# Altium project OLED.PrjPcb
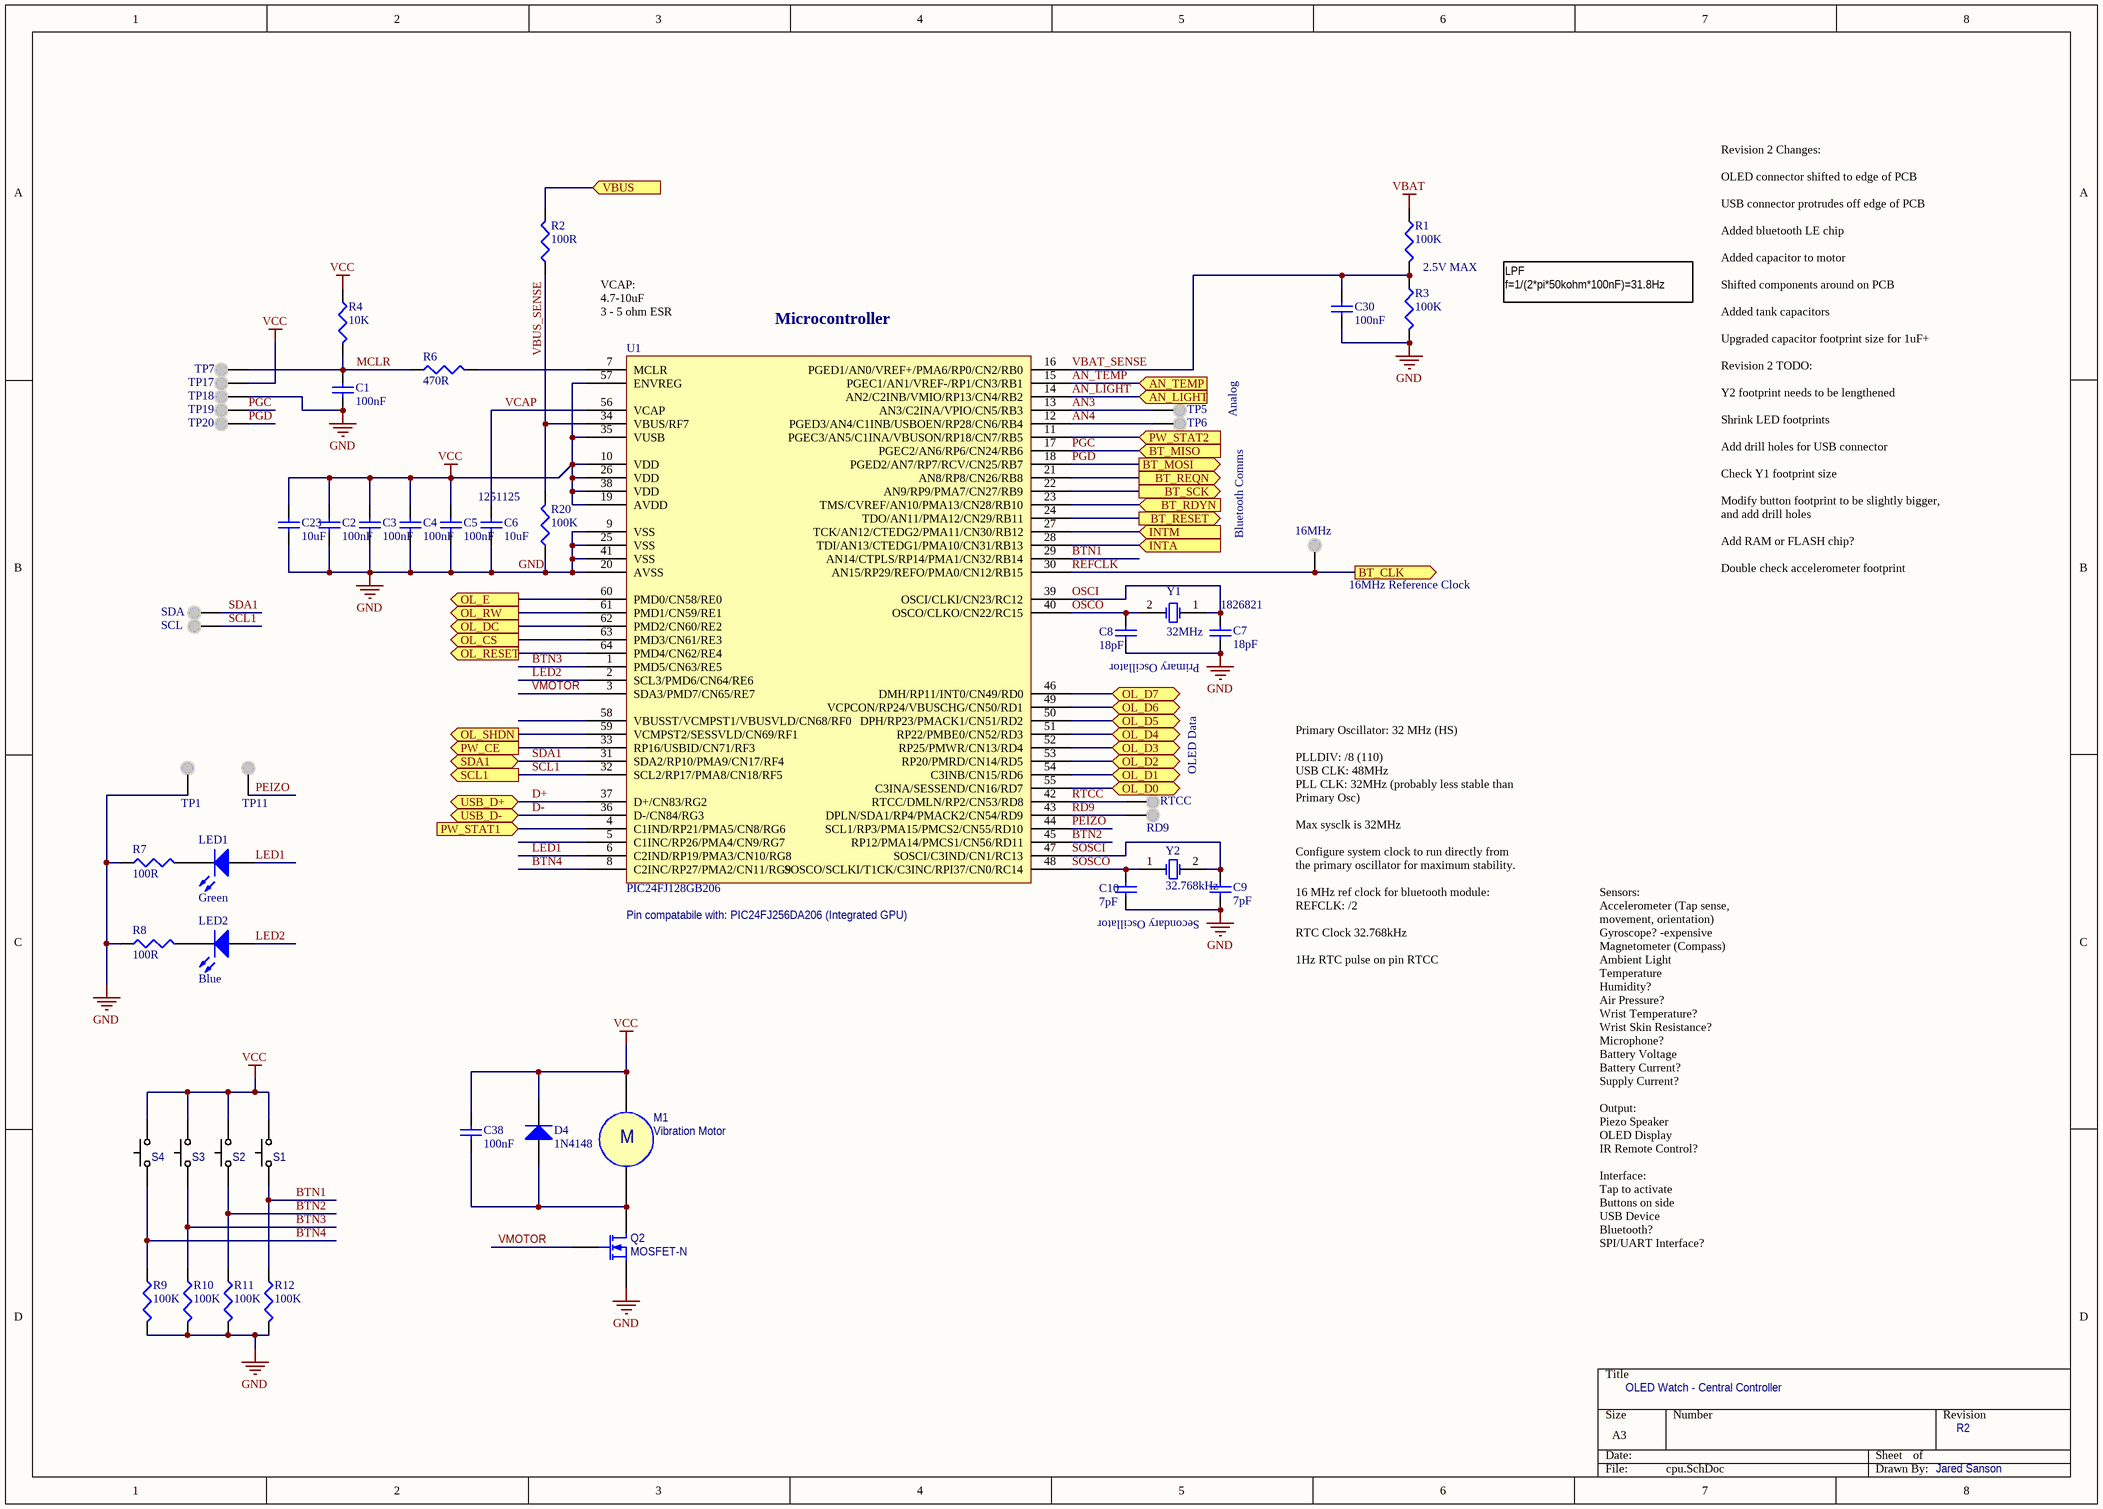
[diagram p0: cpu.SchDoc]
5 sheets, 121 parts. Net scope: flat (ports and power ports of the same name join across sheets).
Board file: pcb.PcbDoc
Sheets:
  cpu.SchDoc
  power.SchDoc
  oled.SchDoc
  sensors.SchDoc
  bluetoothle.SchDoc

## Sheet cpu.SchDoc
size A3

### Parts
C1  value 100nF  [0603C]  (hidden comment: Cap)
C2  value 100nF  [0603C]  (hidden comment: Cap)
C3  value 100nF  [0603C]  (hidden comment: Cap)
C4  value 100nF  [0603C]  (hidden comment: Cap)
C5  value 100nF  [0603C]  (hidden comment: Cap)
C6  value 10uF  Supplier Part Number 1: 1251125  [0805C]  (hidden comment: Cap)
C7  value 18pF  [0603C]  (hidden comment: Cap)
C8  value 18pF  [0603C]  (hidden comment: Cap)
C9  value 7pF  [0603C]  (hidden comment: Cap)
C10  value 7pF  [0603C]  (hidden comment: Cap)
C23  value 10uF  [0805C]  (hidden comment: Cap)
C30  value 100nF  [0603C]  (hidden comment: Cap)
C38  value 100nF  [0603C]  (hidden comment: Cap)
D4  1N4148  [0603D]
LED1  Green  [0603LED]
LED2  Blue  [0603LED]
M1  Vibration Motor  [VIBRATION_MOTOR]
OSC  16MHz  [TESTPOINT_TOP]
Q2  MOSFET-N  [SOT-23B_N]
R1  value 100K  [0603R]  (hidden comment: Res3)
R2  value 100R  [0603R]  (hidden comment: Res3)
R3  value 100K  [0603R]  (hidden comment: Res3)
R4  value 10K  [0603R]  (hidden comment: Res3)
R6  value 470R  [0603R]  (hidden comment: Res3)
R7  value 100R  [0603R]  (hidden comment: Res3)
R8  value 100R  [0603R]  (hidden comment: Res3)
R9  value 100K  [0603R]  (hidden comment: Res3)
R10  value 100K  [0603R]  (hidden comment: Res3)
R11  value 100K  [0603R]  (hidden comment: Res3)
R12  value 100K  [0603R]  (hidden comment: Res3)
R20  value 100K  [0603R]  (hidden comment: Res3)
RD9  (no value)  [TESTPOINT_TOP]
RTCC  RTCC  [TESTPOINT_TOP]  (value not drawn)
S1  SideButton  [SIDE_BUTTON]  (value not drawn)
S2  SideButton  [SIDE_BUTTON]  (value not drawn)
S3  SideButton  [SIDE_BUTTON]  (value not drawn)
S4  SideButton  [SIDE_BUTTON]  (value not drawn)
SCL  SCL  [TESTPOINT_TOP]  (value not drawn)
SDA  SDA  [TESTPOINT_TOP]  (value not drawn)
TP1  PZ-  [TESTPOINT_TOP]  (value not drawn)
TP5  AN4  [TESTPOINT_TOP]  (value not drawn)
TP6  AN5  [TESTPOINT_TOP]  (value not drawn)
TP7  MCLR  [TESTPOINT_TOP]  (value not drawn)
TP11  PZ+  [TESTPOINT_TOP]  (value not drawn)
TP17  VCC  [TESTPOINT_TOP]  (value not drawn)
TP18  GND  [TESTPOINT_TOP]  (value not drawn)
TP19  PGC  [TESTPOINT_TOP]  (value not drawn)
TP20  PGD  [TESTPOINT_TOP]  (value not drawn)
U1  PIC24FJ128GB206  [TQFP_64_10MM]
Y1  32MHz  Supplier Part Number 1: 1826821  [ABRACON32MHZ]
Y2  32.768kHz  [BCY-W2/D1.5]

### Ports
AN_LIGHT (in), AN_TEMP (in), BT_CLK (out), BT_MISO (in), BT_MOSI (out), BT_RDYN (in), BT_REQN (out), BT_RESET (out), BT_SCK (out), INTA (in), INTM (in), OL_CS (out), OL_D0 (bidir), OL_D1 (bidir), OL_D2 (bidir), OL_D3 (bidir), OL_D4 (bidir), OL_D5 (bidir), OL_D6 (bidir), OL_D7 (bidir), OL_DC (out), OL_E (out), OL_RESET (out), OL_RW (out), OL_SHDN (out), PW_CE (out), PW_STAT1 (in), PW_STAT2 (in), SCL1 (out), SDA1 (bidir), USB_D+ (bidir), USB_D- (bidir), VBUS (in)

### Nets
GND: C1.2 C2.2 C3.2 C4.2 C5.2 C6.2 C7.2 C8.2 C9.2 C10.2 C23.2 C30.2 Q2.3(S) R3.2 R7.1 R8.1 R9.2 R10.2 R11.2 R12.2 R20.1 TP1.1(TP) TP18.1(TP) U1.9(VSS) U1.20(AVSS) U1.25(VSS) U1.41(VSS)
VBAT: R1.1
VCC: C2.1 C3.1 C4.1 C5.1 C23.1 C38.1 D4.2(K) M1.1 R4.1 S1.2 S2.2 S3.2 S4.2 TP17.1(TP) U1.10(VDD) U1.19(AVDD) U1.26(VDD) U1.35(VUSB) U1.38(VDD) U1.57(ENVREG)
AN3: TP5.1(TP) U1.13(AN3/C2INA/VPIO/CN5/RB3)
AN4: TP6.1(TP) U1.12(PGED3/AN4/C1INB/USBOEN/RP28/CN6/RB4)
AN_LIGHT: U1.14(AN2/C2INB/VMIO/RP13/CN4/RB2) ; port AN_LIGHT
AN_TEMP: U1.15(PGEC1/AN1/VREF-/RP1/CN3/RB1) ; port AN_TEMP
BT_RDYN: U1.23(TMS/CVREF/AN10/PMA13/CN28/RB10) ; port BT_RDYN
BT_REQN: U1.21(AN8/RP8/CN26/RB8) ; port BT_REQN
BTN1: R12.1 S1.1 U1.29(AN14/CTPLS/RP14/PMA1/CN32/RB14)
BTN2: R11.1 S2.1 U1.45(RP12/PMA14/PMCS1/CN56/RD11)
BTN3: R10.1 S3.1 U1.1(PMD5/CN63/RE5)
BTN4: R9.1 S4.1 U1.8(C2INC/RP27/PMA2/CN11/RG9)
D+: U1.37(D+/CN83/RG2) ; port USB_D+
D-: U1.36(D-/CN84/RG3) ; port USB_D-
INTA: U1.28(TDI/AN13/CTEDG1/PMA10/CN31/RB13) ; port INTA
INTM: U1.27(TCK/AN12/CTEDG2/PMA11/CN30/RB12) ; port INTM
LED1: LED1.1(A) U1.6(C2IND/RP19/PMA3/CN10/RG8)
LED2: LED2.1(A) U1.2(SCL3/PMD6/CN64/RE6)
MCLR: C1.1 R4.2 R6.1 TP7.1(TP)
OL_CS: U1.63(PMD3/CN61/RE3) ; port OL_CS
OL_D0: U1.55(C3INA/SESSEND/CN16/RD7) ; port OL_D0
OL_D1: U1.54(C3INB/CN15/RD6) ; port OL_D1
OL_D2: U1.53(RP20/PMRD/CN14/RD5) ; port OL_D2
OL_D3: U1.52(RP25/PMWR/CN13/RD4) ; port OL_D3
OL_D4: U1.51(RP22/PMBE0/CN52/RD3) ; port OL_D4
OL_D5: U1.50(DPH/RP23/PMACK1/CN51/RD2) ; port OL_D5
OL_D6: U1.49(VCPCON/RP24/VBUSCHG/CN50/RD1) ; port OL_D6
OL_D7: U1.46(DMH/RP11/INT0/CN49/RD0) ; port OL_D7
OL_DC: U1.62(PMD2/CN60/RE2) ; port OL_DC
OL_E: U1.60(PMD0/CN58/RE0) ; port OL_E
OL_RESET: U1.64(PMD4/CN62/RE4) ; port OL_RESET
OL_RW: U1.61(PMD1/CN59/RE1) ; port OL_RW
OL_SHDN: U1.59(VCMPST2/SESSVLD/CN69/RF1) ; port OL_SHDN
OSCI: C7.1 U1.39(OSCI/CLKI/CN23/RC12) Y1.1(OSC1)
OSCO: C8.1 U1.40(OSCO/CLKO/CN22/RC15) Y1.2(OSC2)
PEIZO: TP11.1(TP) U1.44(SCL1/RP3/PMA15/PMCS2/CN55/RD10)
PGC: TP19.1(TP) U1.17(PGEC2/AN6/RP6/CN24/RB6) ; port BT_MISO
PGD: TP20.1(TP) U1.18(PGED2/AN7/RP7/RCV/CN25/RB7) ; port BT_MOSI
PW_CE: U1.33(RP16/USBID/CN71/RF3) ; port PW_CE
RD9: RD9.1(TP) U1.43(DPLN/SDA1/RP4/PMACK2/CN54/RD9)
REFCLK: OSC.1(TP) U1.30(AN15/RP29/REFO/PMA0/CN12/RB15) ; port BT_CLK
RESET: U1.24(TDO/AN11/PMA12/CN29/RB11) ; port BT_RESET
RTCC: RTCC.1(TP) U1.42(RTCC/DMLN/RP2/CN53/RD8)
SCK: U1.22(AN9/RP9/PMA7/CN27/RB9) ; port BT_SCK
SCL1: SCL.1(TP) U1.32(SCL2/RP17/PMA8/CN18/RF5) ; port SCL1
SDA1: SDA.1(TP) U1.31(SDA2/RP10/PMA9/CN17/RF4) ; port SDA1
SOSCI: C9.1 U1.47(SOSCI/C3IND/CN1/RC13) Y2.2(OSC2)
SOSCO: C10.1 U1.48(SOSCO/SCLKI/T1CK/C3INC/RPI37/CN0/RC14) Y2.1(OSC1)
STAT1: U1.4(C1IND/RP21/PMA5/CN8/RG6) ; port PW_STAT1
STAT2: U1.11(PGEC3/AN5/C1INA/VBUSON/RP18/CN7/RB5) ; port PW_STAT2
VBAT_SENSE: C30.1 R1.2 R3.1 U1.16(PGED1/AN0/VREF+/PMA6/RP0/CN2/RB0)
VBUS: R2.2 ; port VBUS
VBUS_SENSE: R2.1 R20.2 U1.34(VBUS/RF7)
VCAP: C6.1 U1.56(VCAP)
VMOTOR: Q2.2(G) U1.3(SDA3/PMD7/CN65/RE7)
NetC38_2: C38.2 D4.1(A) M1.2 Q2.1(D)
NetLED1_2: LED1.2(K) R7.2
NetLED2_2: LED2.2(K) R8.2
NetR6_2: R6.2 U1.7(MCLR)

Not connected (* = marked no-connect by the designer): U1 5(C1INC/RP26/PMA4/CN9/RG7) 58(VBUSST/VCMPST1/VBUSVLD/CN68/RF0)

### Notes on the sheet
- 2.5V MAX
- LPF
  f=1/(2*pi*50kohm*100nF)=31.8Hz
- VCAP:
  4.7-10uF
  3 - 5 ohm ESR
- (near U1) Microcontroller
- Analog
- Bluetooth Comms
- (near OSC) 16MHz Reference Clock
- Primary Oscillator
- OLED Data
- Revision 2 Changes:
  OLED connector shifted to edge of PCB
  USB connector protrudes off edge of PCB
  Added bluetooth LE chip
  Added capacitor to motor
  Shifted components around on PCB
  Added tank capacitors
  Upgraded capacitor footprint size for 1uF+
  Revision 2 TODO:
  Y2 footprint needs to be lengthened
  Shrink LED footprints
  Add drill holes for USB connector
  Check Y1 footprint size
  Modify button footprint to be slightly bigger, and add drill holes
  Add RAM or FLASH chip?
  Double check accelerometer footprint
- (near U1) Pin compatabile with: PIC24FJ256DA206 (Integrated GPU)
- Secondary Oscillator
- Primary Oscillator: 32 MHz (HS)
  PLLDIV: /8 (110)
  USB CLK: 48MHz
  PLL CLK: 32MHz (probably less stable than Primary Osc)
  Max sysclk is 32MHz
  Configure system clock to run directly from the primary oscillator for maximum stability.
  16 MHz ref clock for bluetooth module:
  REFCLK: /2
  RTC Clock 32.768kHz
  1Hz RTC pulse on pin RTCC
- Sensors:
  Accelerometer (Tap sense, movement, orientation)
  Gyroscope? -expensive
  Magnetometer (Compass)
  Ambient Light
  Temperature
  Humidity?
  Air Pressure?
  Wrist Temperature?
  Wrist Skin Resistance?
  Microphone?
  Battery Voltage
  Battery Current?
  Supply Current?
  Output:
  Piezo Speaker
  OLED Display
  IR Remote Control?
  Interface:
  Tap to activate
  Buttons on side
  USB Device
  Bluetooth?
  SPI/UART Interface?
- OLED Watch - Central Controller
- R2
- Jared Sanson

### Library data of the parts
C1-C10 C23 C30 C38 = Cap: Capacitor
D4 = Diode: Default Diode
LED1 LED2 = LED2: Typical RED, GREEN, YELLOW, AMBER GaAs LED
M1 = VibrationMotor
OSC RD9 RTCC SCL SDA TP1 TP5-TP7 TP11 TP17-TP20 = TestPoint: Test Point
Q2 = MOSFET-N: N-Channel MOSFET
R1-R4 R6-R12 R20 = Res3: Resistor
Y1 = XTAL: Crystal Oscillator; Manufacturer: ABRACON; Manufacturer Part Number: ABM3-32.000MHZ-D2Y-T; Description: ABRACON - ABM3-32.000MHZ-D2Y-T - CRYSTAL, 32MHZ, 18PF, SMD
Y2 = XTAL: Crystal Oscillator

## Sheet power.SchDoc
size A4
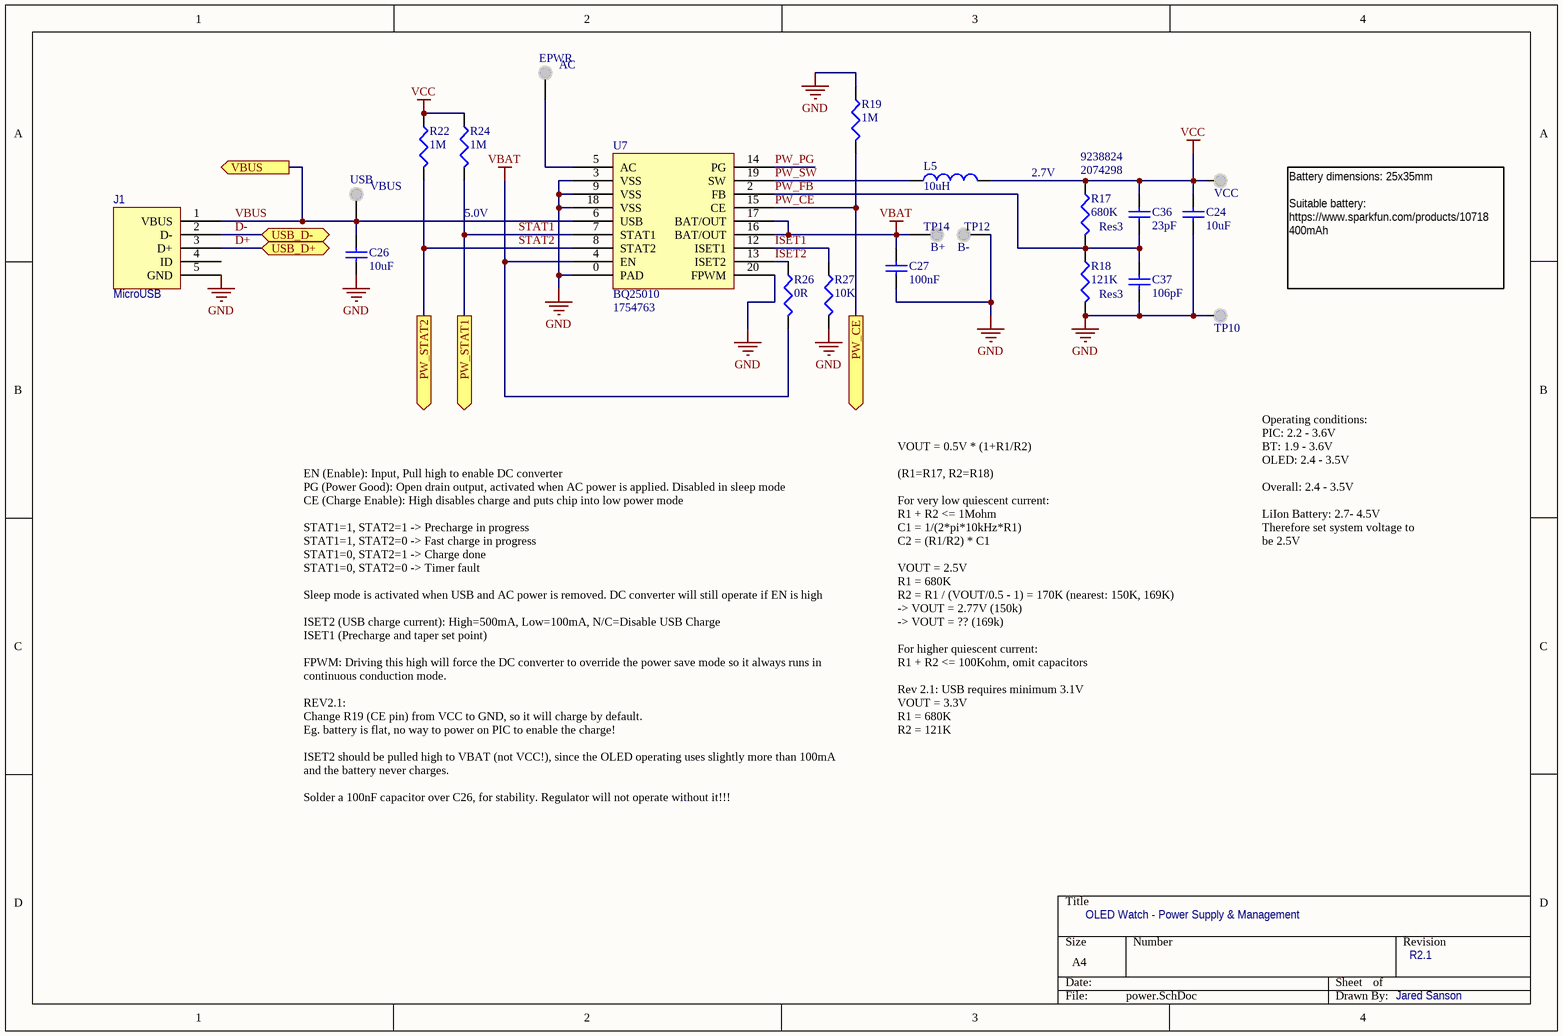
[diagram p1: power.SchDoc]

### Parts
C24  value 10uF  [0805C]  (hidden comment: Cap)
C26  value 10uF  [0805C]  (hidden comment: Cap)
C27  value 100nF  [0603C]  (hidden comment: Cap)
C36  value 23pF  [0603C]  (hidden comment: Cap)
C37  value 106pF  [0603C]  (hidden comment: Cap)
EPWR  AC  [TESTPOINT_TOP]
J1  MicroUSB  [MICRO_USB]
L5  value 10uH  [INDC3225N]  (hidden comment: Inductor)
R17  Res3  value 680K  Supplier Part Number 1: 2074298  Supplier Part Number 2: 9238824  [0603R]
R18  Res3  value 121K  [0603R]
R19  value 1M  [0603R]  (hidden comment: Res3)
R22  value 1M  [0603R]  (hidden comment: Res3)
R24  value 1M  [0603R]  (hidden comment: Res3)
R26  value 0R  [0603R]  (hidden comment: Res3)
R27  value 10K  [0603R]  (hidden comment: Res3)
TP10  GND  [TESTPOINT_TOP]  (value not drawn)
TP12  B-  [TESTPOINT_TOP]
TP14  B+  [TESTPOINT_TOP]
U7  BQ25010  Supplier Part Number 1: 1754763  [RHL]
USB  VBUS  [TESTPOINT_TOP]
VCC  VCC  [TESTPOINT_TOP]  (value not drawn)

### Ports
PW_CE (out), PW_STAT1 (out), PW_STAT2 (out), USB_D+ (bidir), USB_D- (bidir), VBUS (out)

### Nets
GND: C24.2 C26.2 C27.2 C37.2 J1.5(GND) R18.2 R19.1 R27.2 TP10.1(TP) TP12.1(TP) U7.0(PAD) U7.3(VSS) U7.9(VSS) U7.18(VSS) U7.20(FPWM)
VBAT: C27.1 R26.2 TP14.1(TP) U7.4(EN) U7.16(BAT/OUT) U7.17(BAT/OUT)
VCC: C24.1 C36.1 L5.2 R17.1 R22.1 R24.1 VCC.1(TP)
D+: J1.3(D+) ; port USB_D+
D-: J1.2(D-) ; port USB_D-
ISET1: R27.1 U7.12(ISET1)
ISET2: R26.1 U7.13(ISET2)
PW_CE: R19.2 U7.15(CE) ; port PW_CE
PW_FB: C36.2 C37.1 R17.2 R18.1 U7.2(FB)
PW_PG: U7.14(PG)
PW_SW: L5.1 U7.19(SW)
STAT1: R24.2 U7.7(STAT1) ; port PW_STAT1
STAT2: R22.2 U7.8(STAT2) ; port PW_STAT2
VBUS: C26.1 J1.1(VBUS) U7.6(USB) USB.1(TP) ; port VBUS
NetEPWR_1: EPWR.1(TP) U7.5(AC)

Not connected (* = marked no-connect by the designer): J1 4(ID)

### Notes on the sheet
- (near R17) 2.7V
- 5.0V
- Battery dimensions: 25x35mm
  Suitable battery:
  https://www.sparkfun.com/products/10718
  400mAh
- Operating conditions:
  PIC: 2.2 - 3.6V
  BT: 1.9 - 3.6V
  OLED: 2.4 - 3.5V
  Overall: 2.4 - 3.5V
  LiIon Battery: 2.7- 4.5V
  Therefore set system voltage to be 2.5V
- VOUT = 0.5V * (1+R1/R2)
  (R1=R17, R2=R18)
  For very low quiescent current:
  R1 + R2 <= 1Mohm
  C1 = 1/(2*pi*10kHz*R1)
  C2 = (R1/R2) * C1
  VOUT = 2.5V
  R1 = 680K
  R2 = R1 / (VOUT/0.5 - 1) = 170K (nearest: 150K, 169K)
  -> VOUT = 2.77V (150k)
  -> VOUT = ?? (169k)
  For higher quiescent current:
  R1 + R2 <= 100Kohm, omit capacitors
  Rev 2.1: USB requires minimum 3.1V
  VOUT = 3.3V
  R1 = 680K
  R2 = 121K
- EN (Enable): Input, Pull high to enable DC converter
  PG (Power Good): Open drain output, activated when AC power is applied. Disabled in sleep mode
  CE (Charge Enable): High disables charge and puts chip into low power mode
  STAT1=1, STAT2=1 -> Precharge in progress
  STAT1=1, STAT2=0 -> Fast charge in progress
  STAT1=0, STAT2=1 -> Charge done
  STAT1=0, STAT2=0 -> Timer fault
  Sleep mode is activated when USB and AC power is removed. DC converter will still operate if EN is high
  ISET2 (USB charge current): High=500mA, Low=100mA, N/C=Disable USB Charge
  ISET1 (Precharge and taper set point)
  FPWM: Driving this high will force the DC converter to override the power save mode so it always runs in continuous conduction mode.
  REV2.1:
  Change R19 (CE pin) from VCC to GND, so it will charge by default.
  Eg. battery is flat, no way to power on PIC to enable the charge!
  ISET2 should be pulled high to VBAT (not VCC!), since the OLED operating uses slightly more than 100mA and the battery never charges.
  Solder a 100nF capacitor over C26, for stability. Regulator will not operate without it!!!
- OLED Watch - Power Supply & Management
- R2.1
- Jared Sanson

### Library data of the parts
C24 C26 C27 C36 C37 = Cap: Capacitor
EPWR TP10 TP12 TP14 USB VCC = TestPoint: Test Point
L5 = Inductor: Code_IEC: 1005
R17-R19 R22 R24 R26 R27 = Res3: Resistor

## Sheet oled.SchDoc
size A4
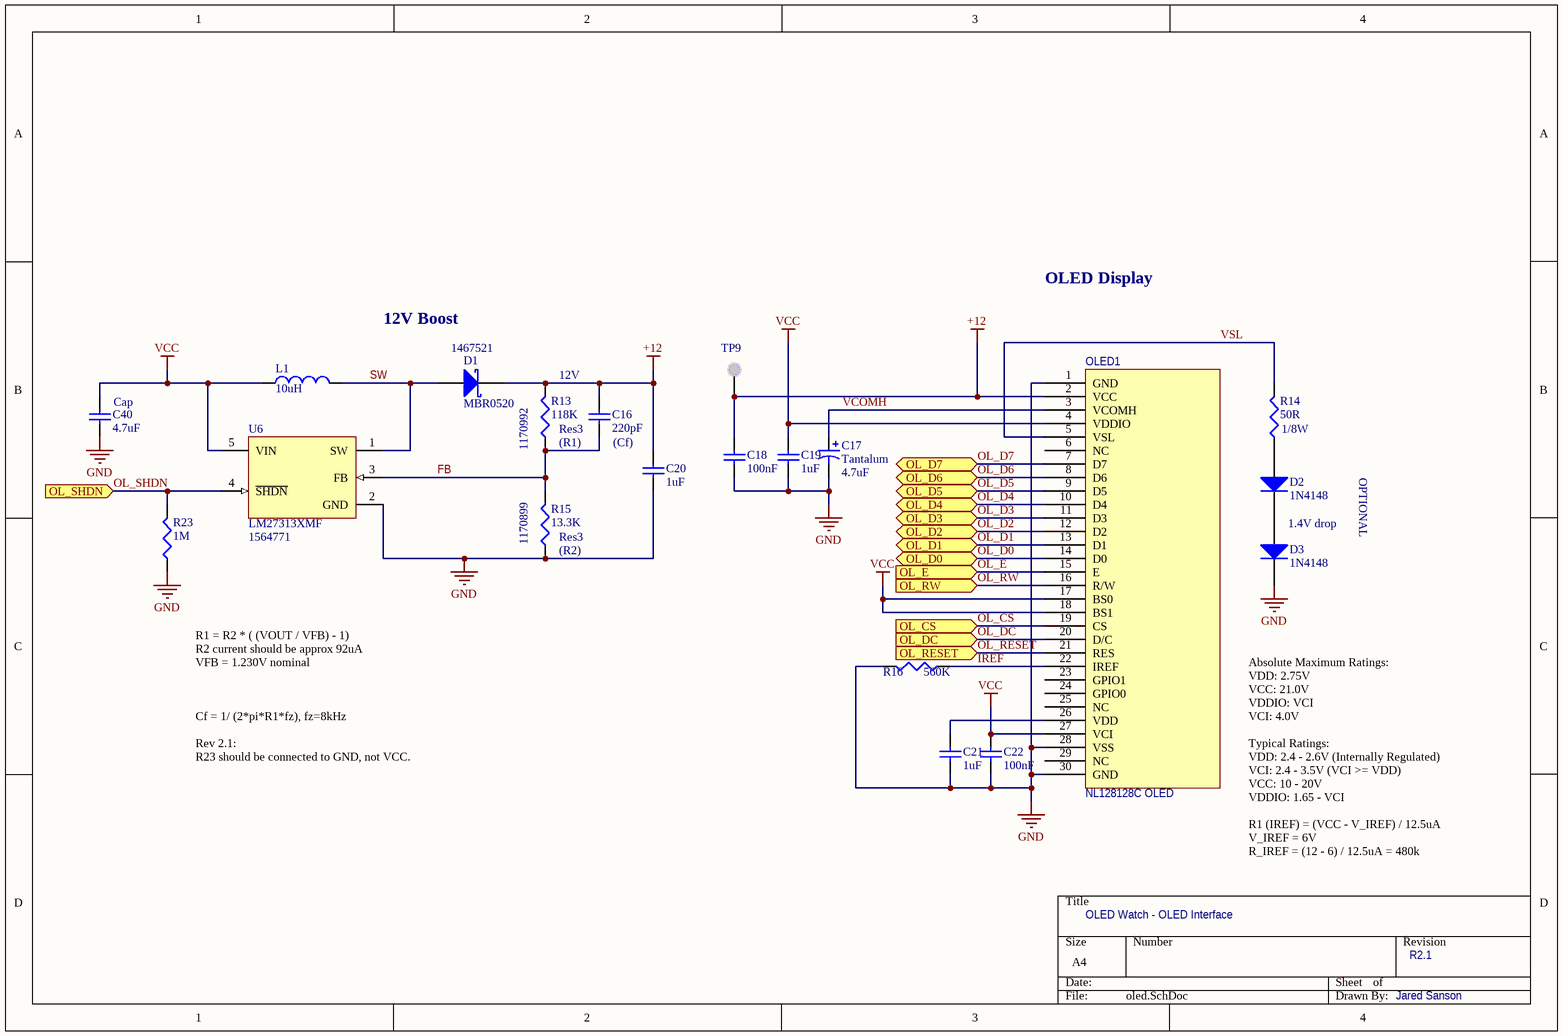
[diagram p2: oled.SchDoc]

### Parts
C16  value 220pF  Variable: (Cf)  [0603C]  (hidden comment: Cap)
C17  Tantalum  value 4.7uF  [0805C]
C18  value 100nF  [0603C]  (hidden comment: Cap)
C19  value 1uF  [0603C]  (hidden comment: Cap)
C20  value 1uF  [0805C]  (hidden comment: Cap)
C21  value 1uF  [0805C]  (hidden comment: Cap)
C22  value 100nF  [0603C]  (hidden comment: Cap)
C40  Cap  value 4.7uF  [0805C]
D1  MBR0520  Supplier Part Number 1: 1467521  [0603D]
D2  1N4148  [0603D]
D3  1N4148  [0603D]
L1  value 10uH  [INDC3225N]  (hidden comment: Inductor)
OLED1  NL128128C OLED  [FFC/SM0.5-2H30]
R13  Res3  value 118K  Variable: (R1)  Supplier Part Number 1: 1170992  [0603R]
R14  value 50R  [0603R]  (hidden comment: Res3)
R15  Res3  value 13.3K  Variable: (R2)  Supplier Part Number 1: 1170899  [0603R]
R16  value 560K  [0603R]  (hidden comment: Res3)
R23  value 1M  [0603R]  (hidden comment: Res3)
TP9  +12  [TESTPOINT_TOP]  (value not drawn)
U6  LM27313XMF  Supplier Part Number 1: 1564771  [MF05A_N]

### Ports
OL_CS (in), OL_D0 (bidir), OL_D1 (bidir), OL_D2 (bidir), OL_D3 (bidir), OL_D4 (bidir), OL_D5 (bidir), OL_D6 (bidir), OL_D7 (bidir), OL_DC (in), OL_E (in), OL_RESET (in), OL_RW (in), OL_SHDN (in)

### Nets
+12: C16.1 C18.1 C20.1 D1.2(K) OLED1.2(VCC) R13.2 TP9.1(TP)
GND: C17.2 C18.2 C19.2 C20.2 C21.2 C22.2 C40.2 D3.2(K) OLED1.1(GND) OLED1.28(VSS) OLED1.30(GND) R15.1 R16.2 R23.1 U6.2(GND)
VCC: C19.1 C22.1 C40.1 L1.1 OLED1.4(VDDIO) OLED1.17(BS0) OLED1.18(BS1) OLED1.27(VCI) U6.5(VIN)
FB: C16.2 R13.1 R15.2 U6.3(FB)
IREF: OLED1.22(IREF) R16.1
OL_CS: OLED1.19(CS) ; port OL_CS
OL_D0: OLED1.14(D0) ; port OL_D0
OL_D1: OLED1.13(D1) ; port OL_D1
OL_D2: OLED1.12(D2) ; port OL_D2
OL_D3: OLED1.11(D3) ; port OL_D3
OL_D4: OLED1.10(D4) ; port OL_D4
OL_D5: OLED1.9(D5) ; port OL_D5
OL_D6: OLED1.8(D6) ; port OL_D6
OL_D7: OLED1.7(D7) ; port OL_D7
OL_DC: OLED1.20(D/C) ; port OL_DC
OL_E: OLED1.15(E) ; port OL_E
OL_RESET: OLED1.21(RES) ; port OL_RESET
OL_RW: OLED1.16(R/W) ; port OL_RW
OL_SHDN: R23.2 U6.4(~{SHDN}) ; port OL_SHDN
SW: D1.1(A) L1.2 U6.1(SW)
VCOMH: C17.1 OLED1.3(VCOMH)
VSL: OLED1.5(VSL) R14.2
NetC21_1: C21.1 OLED1.26(VDD)
NetD2_1: D2.1(A) R14.1
NetD2_2: D2.2(K) D3.1(A)

Not connected (* = marked no-connect by the designer): OLED1 6(NC) 23(GPIO1) 24(GPIO0) 25(NC) 29(NC)

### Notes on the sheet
- OLED Display
- 12V Boost
- (near R13) 12V
- (near R14) 1/8W
- OPTIONAL
- 1.4V drop
- R1 = R2 * ( (VOUT / VFB) - 1)
  R2 current should be approx 92uA
  VFB = 1.230V nominal
  Cf = 1/ (2*pi*R1*fz), fz=8kHz
  Rev 2.1:
  R23 should be connected to GND, not VCC.
- OLED Watch - OLED Interface
- Absolute Maximum Ratings:
  VDD: 2.75V
  VCC: 21.0V
  VDDIO: VCI
  VCI: 4.0V
  Typical Ratings:
  VDD: 2.4 - 2.6V (Internally Regulated)
  VCI: 2.4 - 3.5V (VCI >= VDD)
  VCC: 10 - 20V
  VDDIO: 1.65 - VCI
  R1 (IREF) = (VCC - V_IREF) / 12.5uA
  V_IREF = 6V
  R_IREF = (12 - 6) / 12.5uA = 480k
- R2.1
- Jared Sanson

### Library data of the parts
C16 C18-C22 C40 = Cap: Capacitor
C17 = Cap Pol1: Polarized Capacitor (Radial)
D1 = D Schottky: Schottky Diode
D2 D3 = Diode: Default Diode
L1 = Inductor: Code_IEC: 1005
OLED1 = NL128128C: 128x128 OLED Display
R13-R16 R23 = Res3: Resistor
TP9 = TestPoint: Test Point
U6 = LM27313XMF: 1.6 MHz Boost Converter With 30V Internal FET Switch in SOT-23; Manufacturer: National Semiconductor; CompType: Switcher; PackageTopMarking: SRPB*XTT; PowerWise: N

## Sheet sensors.SchDoc
size A4
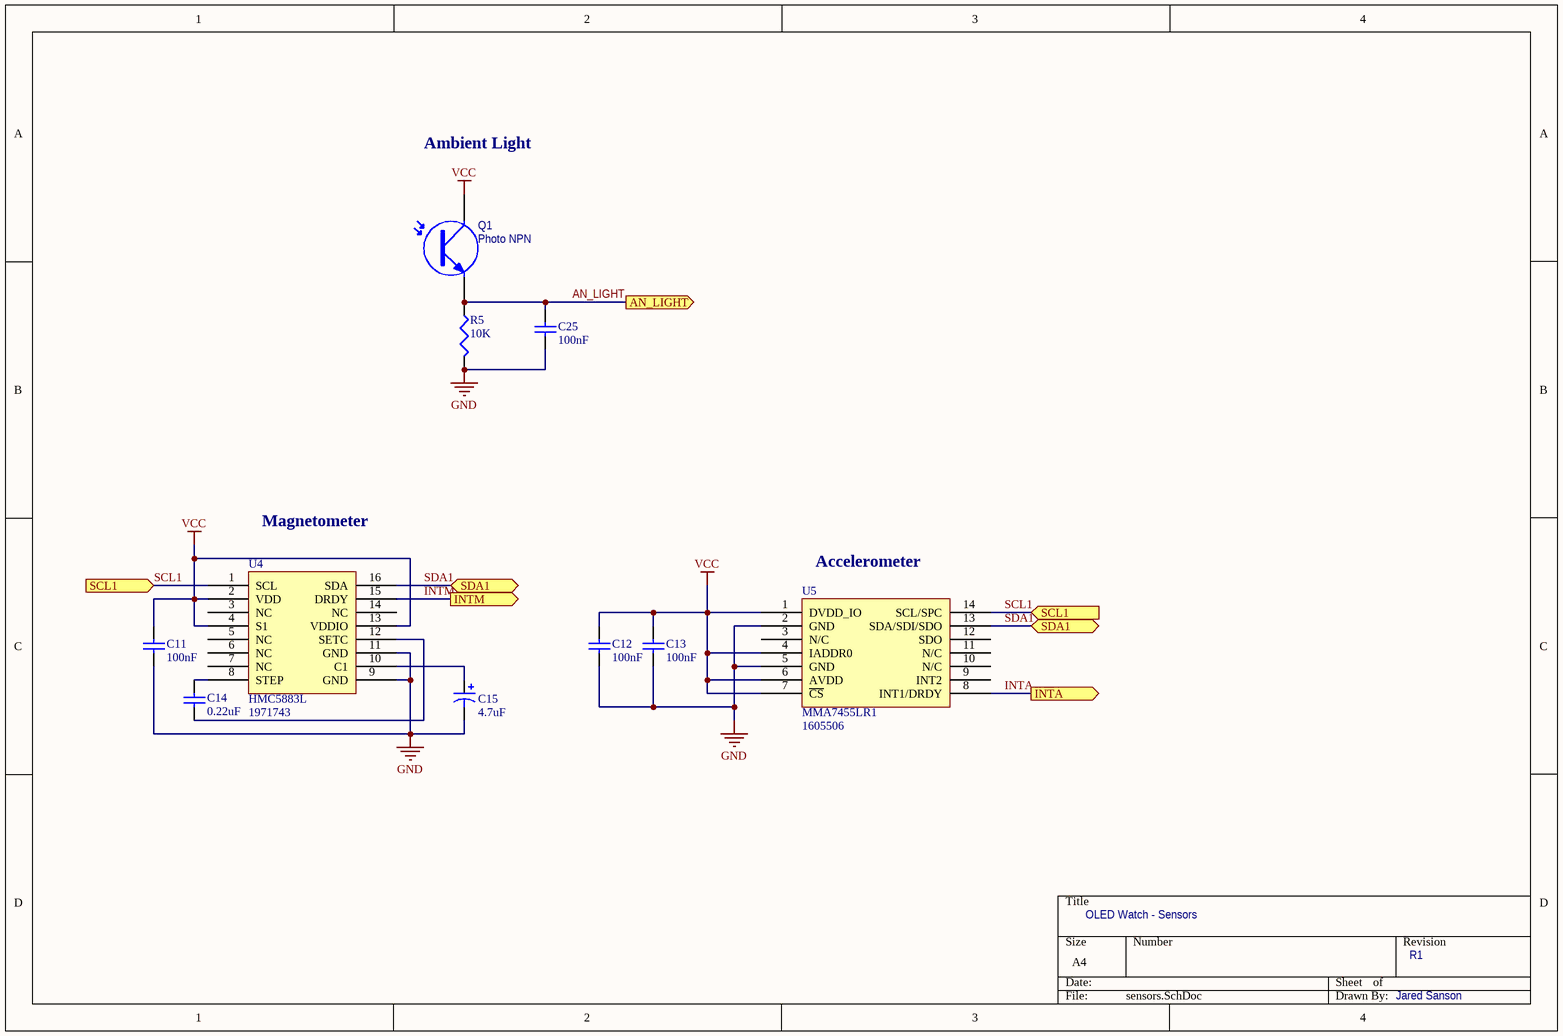
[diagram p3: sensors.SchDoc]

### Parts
C11  value 100nF  [0603C]  (hidden comment: Cap)
C12  value 100nF  [0603C]  (hidden comment: Cap)
C13  value 100nF  [0603C]  (hidden comment: Cap)
C14  value 0.22uF  [0603C]  (hidden comment: Cap)
C15  value 4.7uF  [0805C]  (hidden comment: Cap Pol1)
C25  value 100nF  [0603C]  (hidden comment: Cap)
Q1  Photo NPN  [TEMT6000]
R5  value 10K  [0603R]  (hidden comment: Res3)
U4  HMC5883L  Supplier Part Number 1: 1971743  [HMC5883L_16PINQFN]
U5  MMA7455LR1  Supplier Part Number 1: 1605506  [LGA80P500X300-14N]

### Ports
AN_LIGHT (out), INTA (out), INTM (out), SCL1 (in), SDA1 (bidir)

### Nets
GND: C11.2 C12.2 C13.2 C15.2 C25.2 R5.2 U4.9(GND) U4.11(GND) U5.2(GND) U5.5(GND)
VCC: C11.1 C12.1 C13.1 Q1.1(C) U4.2(VDD) U4.4(S1) U4.13(VDDIO) U5.1(DVDD_IO) U5.4(IADDR0) U5.6(AVDD) U5.7(~{CS})
AN_LIGHT: C25.1 Q1.3(E) R5.1 ; port AN_LIGHT
INTA: U5.8(INT1/DRDY) ; port INTA
INTM: U4.15(DRDY) ; port INTM
SCL1: U4.1(SCL) U5.14(SCL/SPC) ; port SCL1
SDA1: U4.16(SDA) U5.13(SDA/SDI/SDO) ; port SDA1
NetC14_1: C14.1 U4.12(SETC)
NetC14_2: C14.2 U4.8(STEP)
NetC15_1: C15.1 U4.10(C1)

Not connected (* = marked no-connect by the designer): U4 3(NC) 5(NC) 6(NC) 7(NC) 14(NC); U5 3(N/C) 9(INT2) 10(N/C) 11(N/C) 12(SDO)

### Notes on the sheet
- Ambient Light
- Magnetometer
- (near U5) Accelerometer
- OLED Watch - Sensors
- R1
- Jared Sanson

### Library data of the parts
C11-C14 C25 = Cap: Capacitor
C15 = Cap Pol1: Polarized Capacitor (Radial)
Q1 = Photo NPN: NPN Phototransistor
R5 = Res3: Resistor
U4 = HMC5883L: Honeywell 3 Axis Magnetometer; Manufacturer: HONEYWELL M&PS; Manufacturer Part Number: HMC5883L-TR; Description: HONEYWELL M&PS - HMC5883L-TR - SENSOR, MAGNETIC, 3AXIS, 16 PIN; Magnetic Field Min: -8; Magnetic Field Max: 8; Resolution (Gauss): 0.005; Interface Type: I2; Magnetometer Range: -8G to 8; Supply Voltage Range: 2.16V DC to 3.6
U5 = MMA7455LR1: 3-Axis Accelerometer, 5g; Manufacturer: FREESCALE SEMICONDUCTOR; Description: FREESCALE SEMICONDUCTOR - MMA7455LR1 - IC, 3-AXIS DIGITAL 2, 4, 8G, 14-LGA; MEMS Sensor Output: Digital; Measurement Axis: X, Y, Z; Acceleration Range: ± 2g, ± 4g, ± 8; Supply Voltage Min: 2.4; Supply Voltage Max: 3.6; Sensor Case Style: LGA; No. of Pins: 14; Sensitivity Min: 58counts/g, 29counts/g, 14.5; Sensitivity Typ: 16counts/g, 32counts/g, 64; Sensitivity Max: 70counts/g, 35counts/g, 17.5; SVHC: No SVHC (19-Dec-2012); Amplifier Type: Accelerometer Sensor X-Y-Z axis; Interface Type: I2; No. of Bits: 10; No. of Channels: 3; Supply Current: 400; Supply Voltage Range: 2.4V to 3.6

## Sheet bluetoothle.SchDoc
size A4
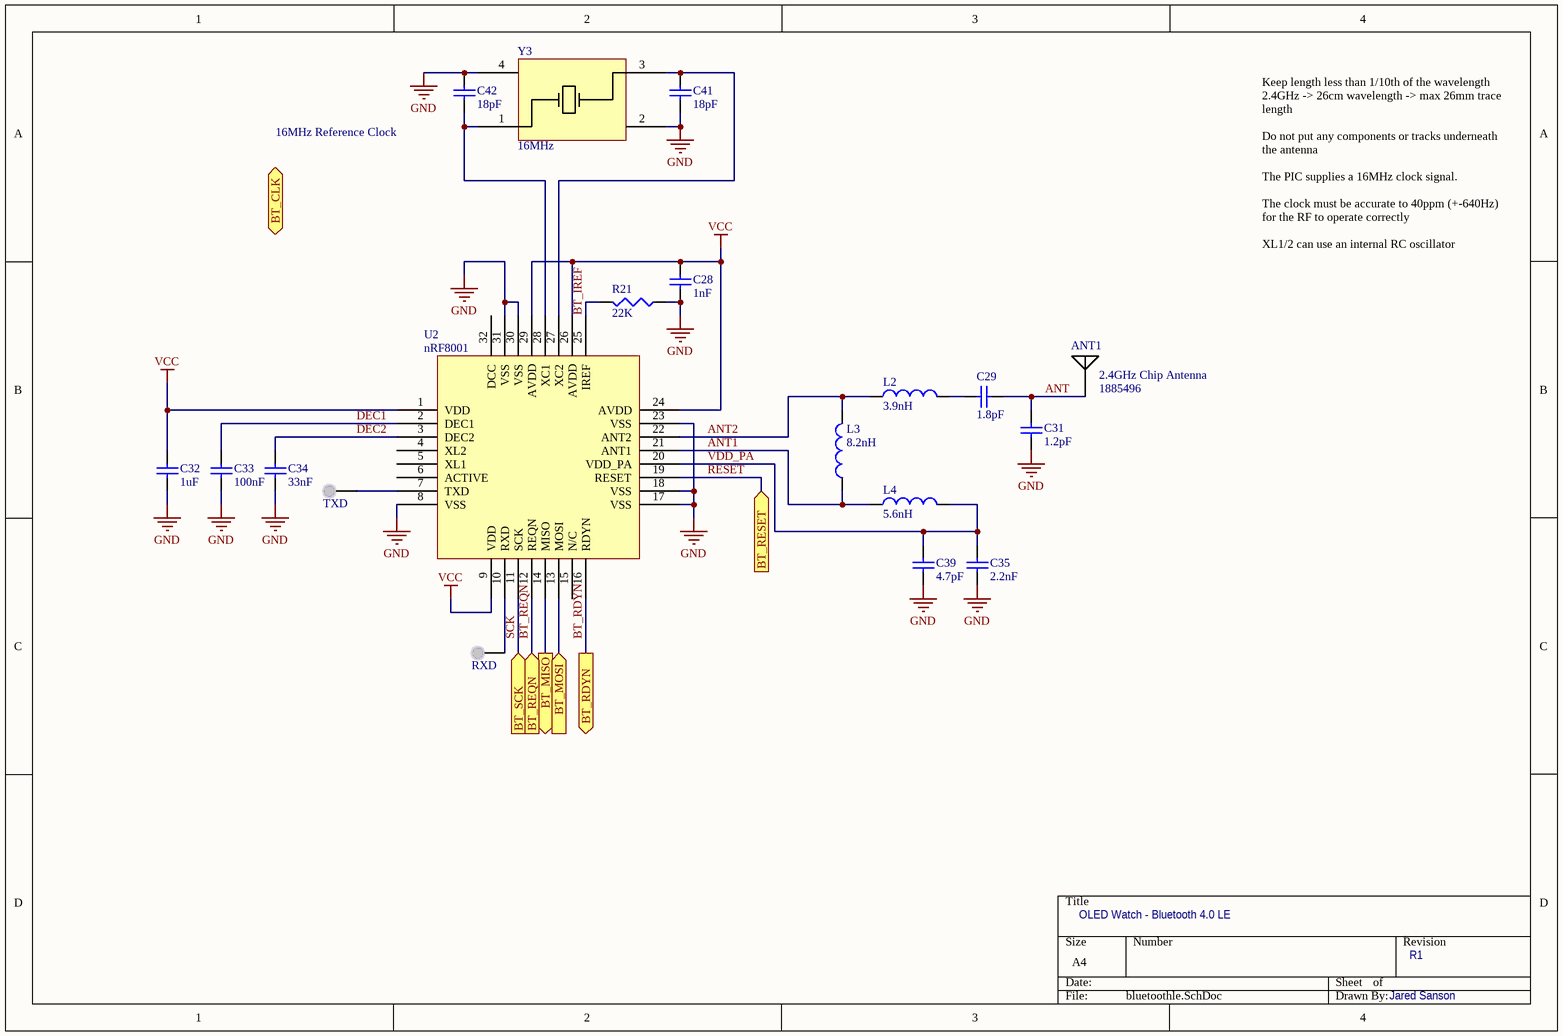
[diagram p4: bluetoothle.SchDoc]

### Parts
ANT1  2.4GHz Chip Antenna  Supplier Part Number 1: 1885496  [2450AT18A100E]
C28  value 1nF  [0603C]  (hidden comment: Cap)
C29  value 1.8pF  [0603C]  (hidden comment: Cap)
C31  value 1.2pF  [0603C]  (hidden comment: Cap)
C32  value 1uF  [0805C]  (hidden comment: Cap)
C33  value 100nF  [0603C]  (hidden comment: Cap)
C34  value 33nF  [0603C]  (hidden comment: Cap)
C35  value 2.2nF  [0603C]  (hidden comment: Cap)
C39  value 4.7pF  [0603C]  (hidden comment: Cap)
C41  value 18pF  [0603C]  (hidden comment: Cap)
C42  value 18pF  [0603C]  (hidden comment: Cap)
L2  value 3.9nH  [0603L]  (hidden comment: Inductor)
L3  value 8.2nH  [0603L]  (hidden comment: Inductor)
L4  value 5.6nH  [0603L]  (hidden comment: Inductor)
R21  value 22K  [0603R]  (hidden comment: Res3)
RXD  AN4  [TESTPOINT_TOP]  (value not drawn)
TXD  AN4  [TESTPOINT_TOP]  (value not drawn)
U2  nRF8001  [QFN50P500X500-32V5N]
Y3  value 16MHz  [TXC-16MHZ]  (hidden comment: TXC-16MHz)

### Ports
BT_CLK (in), BT_MISO (out), BT_MOSI (in), BT_RDYN (out), BT_REQN (in), BT_RESET (in), BT_SCK (in)

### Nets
GND: C28.1 C31.1 C32.2 C33.2 C34.2 C35.2 C39.2 C41.1 C42.2 R21.1 U2.8(VSS) U2.17(VSS) U2.18(VSS) U2.23(VSS) U2.30(VSS) U2.31(VSS) Y3.2 Y3.4
VCC: C28.2 C32.1 U2.1(VDD) U2.9(VDD) U2.24(AVDD) U2.26(AVDD) U2.29(AVDD)
ANT: ANT1.1 C29.2 C31.2
ANT1: L3.1 L4.1 U2.21(ANT1)
ANT2: L2.1 L3.2 U2.22(ANT2)
BT_IREF: R21.2 U2.25(IREF)
BT_RDYN: U2.16(RDYN) ; port BT_RDYN
BT_REQN: U2.12(REQN) ; port BT_REQN
DEC1: C33.1 U2.2(DEC1)
DEC2: C34.1 U2.3(DEC2)
PGC: U2.14(MISO) ; port BT_MISO
PGD: U2.13(MOSI) ; port BT_MOSI
RESET: U2.19(RESET) ; port BT_RESET
SCK: U2.11(SCK) ; port BT_SCK
VDD_PA: C35.1 C39.1 L4.2 U2.20(VDD_PA)
NetC29_1: C29.1 L2.2
NetC41_2: C41.2 U2.27(XC2) Y3.3
NetC42_1: C42.1 U2.28(XC1) Y3.1
NetRXD_1: RXD.1(TP) U2.10(RXD)
NetTXD_1: TXD.1(TP) U2.7(TXD)

Not connected (* = marked no-connect by the designer): U2 4(XL2) 5(XL1) 6(ACTIVE) 15(N/C) 32(DCC)

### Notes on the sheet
- 16MHz Reference Clock
- Keep length less than 1/10th of the wavelength
  2.4GHz -> 26cm wavelength -> max 26mm trace length
  Do not put any components or tracks underneath the antenna
  The PIC supplies a 16MHz clock signal.
  The clock must be accurate to 40ppm (+-640Hz) for the RF to operate correctly
  XL1/2 can use an internal RC oscillator
- OLED Watch - Bluetooth 4.0 LE
- R1
- Jared Sanson

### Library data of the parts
ANT1 = 2450AT18A100E: Manufacturer: JOHANSON TECHNOLOGY; Description: JOHANSON TECHNOLOGY - 2450AT18A100E - ANTENNA, CERAMIC, 2.45GHZ
C28 C29 C31-C35 C39 C41 C42 = Cap: Capacitor
L2-L4 = Inductor: Code_IEC: 1005
R21 = Res3: Resistor
RXD TXD = TestPoint: Test Point
Y3 = CrystalTXC

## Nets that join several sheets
GND: cpu (27 pins), power (15 pins), oled (15 pins), sensors (10 pins), bluetoothle (18 pins)
VBAT: cpu (R1.1), power (6 pins)
VCC: cpu (20 pins), power (7 pins), oled (9 pins), sensors (11 pins), bluetoothle (7 pins)
AN_LIGHT: cpu (U1.14), sensors (C25.1 Q1.3 R5.1)
BT_RDYN: cpu (U1.23), bluetoothle (U2.16)
BT_REQN: cpu (U1.21), bluetoothle (U2.12)
D+: cpu (U1.37), power (J1.3)
D-: cpu (U1.36), power (J1.2)
INTA: cpu (U1.28), sensors (U5.8)
INTM: cpu (U1.27), sensors (U4.15)
OL_CS: cpu (U1.63), oled (OLED1.19)
OL_D0: cpu (U1.55), oled (OLED1.14)
OL_D1: cpu (U1.54), oled (OLED1.13)
OL_D2: cpu (U1.53), oled (OLED1.12)
OL_D3: cpu (U1.52), oled (OLED1.11)
OL_D4: cpu (U1.51), oled (OLED1.10)
OL_D5: cpu (U1.50), oled (OLED1.9)
OL_D6: cpu (U1.49), oled (OLED1.8)
OL_D7: cpu (U1.46), oled (OLED1.7)
OL_DC: cpu (U1.62), oled (OLED1.20)
OL_E: cpu (U1.60), oled (OLED1.15)
OL_RESET: cpu (U1.64), oled (OLED1.21)
OL_RW: cpu (U1.61), oled (OLED1.16)
OL_SHDN: cpu (U1.59), oled (R23.2 U6.4)
PGC: cpu (TP19.1 U1.17), bluetoothle (U2.14)
PGD: cpu (TP20.1 U1.18), bluetoothle (U2.13)
PW_CE: cpu (U1.33), power (R19.2 U7.15)
RESET: cpu (U1.24), bluetoothle (U2.19)
SCK: cpu (U1.22), bluetoothle (U2.11)
SCL1: cpu (SCL.1 U1.32), sensors (U4.1 U5.14)
SDA1: cpu (SDA.1 U1.31), sensors (U4.16 U5.13)
STAT1: cpu (U1.4), power (R24.2 U7.7)
STAT2: cpu (U1.11), power (R22.2 U7.8)
VBUS: cpu (R2.2), power (C26.1 J1.1 U7.6 USB.1)

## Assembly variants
Default: all parts fitted
No Bluetooth: not fitted Q1 R5 U2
